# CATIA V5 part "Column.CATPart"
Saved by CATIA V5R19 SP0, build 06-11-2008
Part number: Column
Bounding box of the stored display mesh (mm): x -75 to 75, y -75 to 75, z -500 to 500
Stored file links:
  D:\Shriniwas\v5_r19\c16_CAT_v5r19\c16_Part\Stearing msm\Column.CATPart
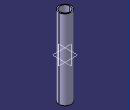
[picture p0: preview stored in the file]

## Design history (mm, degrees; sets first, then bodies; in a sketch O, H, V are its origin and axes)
Body1 (main body)
  Sketch1 on xy-plane, origin (0, 0, 0), H (1, 0, 0), V (0, 1, 0)
    circle A1 centre (0, 0) radius 62.5
    circle A2 centre (0, 0) radius 75
    radius A2 = 75
    radius A1 = 62.5
  Pad1: profile Sketch1, direction (0, 0, 1), length 500, mirrored extent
